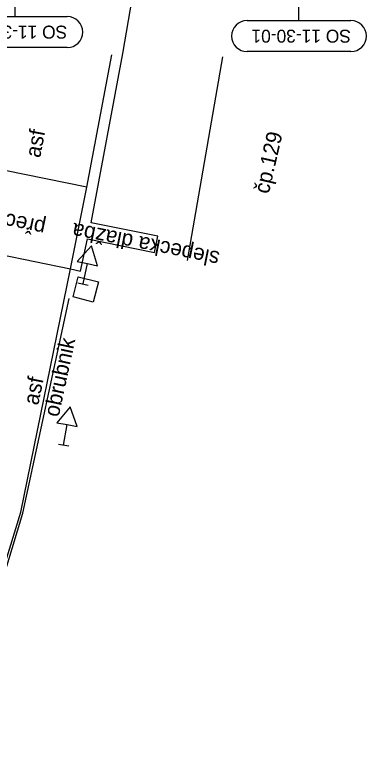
# Model space of a CAD drawing. Extents: x -728800 to -728100, y -1073200 to -1072700.
# Drawn here: x -728508.97 to -728492.04, y -1073092.03 to -1073056.81 of the extents above; entities that cross this region are included whole.
import ezdxf

# ---------------------------------------------------------------- set-up
doc = ezdxf.new("R2010")
doc.units = 0
doc.layers.add('B6_JŽM', color=7, linetype='Continuous')
doc.layers.add('KTA_členění PS a SO', color=7, linetype='Continuous')

msp = doc.modelspace()

# ---------------------------------------------------------------- linework, layer by layer
at = {"layer": 'B6_JŽM'}
for p, q in [((-728500.652, -1073068.652), (-728498.943, -1073058.837)), ((-728505.92, -1073069.734), (-728505.432, -1073069.84)), ((-728506.858, -1073077.515), (-728506.364, -1073077.597))]:
    msp.add_line(p, q, dxfattribs=at)
for points in [[(-728506.273, -1073069.065), (-728505.797, -1073069.171), (-728505.457, -1073067.617), (-728502.232, -1073068.271), (-728502.075, -1073067.494), (-728505.291, -1073066.851), (-728503.761, -1073058.691), (-728502.856, -1073053.426), (-728499.794, -1073053.909), (-728499.714, -1073053.554)], [(-728505.498, -1073065.132), (-728504.293, -1073058.749)], [(-728505.498, -1073065.132), (-728512.38, -1073063.734), (-728513.171, -1073067.654), (-728506.273, -1073069.065), (-728505.498, -1073065.132)], [(-728505.676, -1073069.787), (-728505.463, -1073068.81), (-728504.975, -1073068.916), (-728505.277, -1073067.955), (-728505.952, -1073068.704), (-728505.463, -1073068.81)], [(-728518.577, -1073107.972), (-728511.413, -1073089.698), (-728508.676, -1073080.788), (-728506.273, -1073069.065)], [(-728505.905, -1073069.447), (-728504.937, -1073069.695), (-728505.185, -1073070.663), (-728506.153, -1073070.415), (-728505.905, -1073069.447)], [(-728518.469, -1073107.966), (-728511.248, -1073089.672), (-728508.568, -1073080.832), (-728506.346, -1073070.488)], [(-728506.611, -1073077.556), (-728506.447, -1073076.57), (-728505.954, -1073076.652), (-728506.304, -1073075.706), (-728506.94, -1073076.488), (-728506.447, -1073076.57)]]:
    msp.add_lwpolyline(points, dxfattribs=at)
at = {"layer": 'KTA_členění PS a SO'}
for p, q in [((-728508.938, -1073056.9), (-728508.938, -1073054.9)), ((-728495.283, -1073057.094), (-728495.283, -1073055.094))]:
    msp.add_line(p, q, dxfattribs=at)
for points in [[(-728511.438, -1073056.9), (-728506.438, -1073056.9)], [(-728497.783, -1073057.094), (-728492.783, -1073057.094)], [(-728506.438, -1073058.4), (-728511.438, -1073058.4)], [(-728492.783, -1073058.594), (-728497.783, -1073058.594)]]:
    msp.add_lwpolyline(points, dxfattribs=at)
for centre, start, end in [((-728506.444, -1073057.65), 270.4529, 89.5471), ((-728497.777, -1073057.844), 90.4529, 269.5471), ((-728492.789, -1073057.844), 270.4529, 89.5471)]:
    msp.add_arc(centre, 0.75, start, end, dxfattribs=at)

# ---------------------------------------------------------------- texts
at = {"layer": 'B6_JŽM'}
for s, rotation, p in [('asf', 79.3094, (-728507.742, -1073063.742)), ('čp.129', 77.1025, (-728496.74, -1073065.484)), ('přechod', 168.5173, (-728507.432, -1073066.758)), ('slepecka dlažba', 168.6935, (-728499.062, -1073068.25)), ('obrubnik', 77.8765, (-728506.852, -1073076.234)), ('asf', 78.4159, (-728507.836, -1073075.667))]:
    msp.add_text(s, height=0.75, rotation=rotation, dxfattribs=at).set_placement(p)
at = {"layer": 'KTA_členění PS a SO'}
for p in [(-728506.439, -1073057.341), (-728492.784, -1073057.536)]:
    msp.add_text('SO 11-30-01', height=0.625, rotation=180, dxfattribs=at).set_placement(p)

doc.saveas('drawing.dxf')
